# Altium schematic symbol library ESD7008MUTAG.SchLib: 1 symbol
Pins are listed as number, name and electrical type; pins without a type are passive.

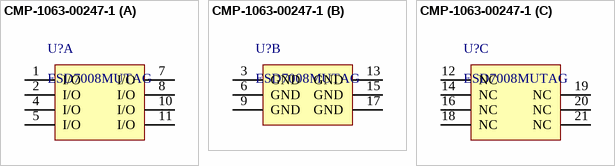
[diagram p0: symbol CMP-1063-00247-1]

## CMP-1063-00247-1
designator U?, comment ESD7008MUTAG
Transient Voltage Suppressor, Low Capacitance ESD Protection for High Speed Data, 18-Pin UDFN, Pb-Free, Tape and Reel; Manufacturer: On Semiconductor; VRWM Max (V): 5; V(BR) Min (V): 5.5; Direction: Bidirectional; Number of Lines: 8; IR Max (uA): 1
footprint ONSC-UDFN-18-517BV_V (SON, 18-Leads, Body 5.5x1.5mm)
part A pins: 1 I/O, 2 I/O, 4 I/O, 5 I/O, 7 I/O, 8 I/O, 10 I/O, 11 I/O
part B pins: 3 GND (power), 6 GND (power), 9 GND (power), 13 GND (power), 15 GND (power), 17 GND (power)
part C pins: 12 NC, 14 NC, 16 NC, 18 NC, 19 NC, 20 NC, 21 NC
